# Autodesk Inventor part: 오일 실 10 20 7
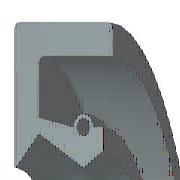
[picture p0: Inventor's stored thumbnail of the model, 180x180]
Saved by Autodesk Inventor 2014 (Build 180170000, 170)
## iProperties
IsCustomPart: 1
Created: 2012-02
Part Number: 오일 실 10 20 7
Material: 고무
Description: 오일-실
Document SubType Name: Modeling
Standard: KS B 2804
Designer: mduedu
Standards Organization: KS
Language: ko-KR
Size Designation: D - 10 20 7
Categories: <MemberInstance><Categories><Category DisplayName="샤프트 부품" InternalName="7f7aeb1f-a693-4053-b835-cee3144e0d98" Mnemonic="SHFT"><Category DisplayName="실링" Intern
Density: 0.93 g/cm^3
Mass: 1.11329 g
Surface Area: 16.3871 cm^2
Volume: 1.19708 cm^3
Appearance: Pink
Author: mduedu
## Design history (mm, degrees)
revolve "본체" stored, may be unused: angle "d17" = 90 deg
revolve "스프링1" stored, may be unused: angle "d18" = 90 deg
body "Solid1"
sketch "스케치1"
  geometry: L1 (0, 10)-(7, 10); L2 (7, 8.25)-(1.75, 8.25); L3 (1.75, 6.75)-(4.9, 5); L4 (4.9, 5)-(0, 5); L5 (0, 0)-(9.586, 0) reference; L6 (4.9, 5)-(6.3, 5.875); L7 (0, 18)-(0, -3) reference; L8 (-1.941, 0)-(11.507, 0) reference; L9 (4.2, 7.1)-(1.75, 7.59); L10 (1.75, 7.59)-(1.75, 8.25); L11 (0, 10)-(0, 5.088); L12 (4.9, 5)-(0, 5); L13 (1.75, 6.75)-(0.152, 5.028); L14 (7, 10)-(7, 8.25); L15 (5.6, 7.1)-(6.3, 7.1); L16 (6.3, 7.1)-(6.3, 5.875); C1 r 0.455 at (4.9, 7.1); A1 r 0.7 centre (4.9, 7.1) between (5.6, 7.1) and (4.2, 7.1); A2 r 0.088 centre (0.088, 5.088) between (0, 5.088) and (0.152, 5.028); 1 further point
  constraints: 28 end point, 5 horizontal alignment, 5 point on line, 4 point on circle, 4 vertical alignment, 3 centre point, 3 tangent, 2 collinear, 2 horizontal, 2 perpendicular, 1 coincident, 1 parallel
  dimensions: "d0" = 20 diameter of L1 L5 (= SD2); "d1" = 1.75 distance of L1.end L2.start (= SD); "d2" = 0.91 diameter of C1 (= SPDI); "d3" = 1.4 diameter of A1 (= SPDA); "d4" = 10 diameter of L3.end L5 (= NND); "d5" = 13.5 diameter of L3.start L5 (= TKDM); "d7" = 15.18 diameter of L9.end L5 (= TKDM + 0.24 x SWDT); "d8" = 1.75 distance between parallel lines of L11 L10 (= SD); "d9" = 4.9 distance from line of L11 C1.centre (= SPDST); "d10" = 14.2 diameter of C1.centre L5 (= HLDM); "d11" = 0.0875 radius of A2 (= 0.25 x LAB); "d12" = 6.3 distance between parallel lines of L11 L16 (= SDI); "d13" = 11.75 diameter of L6.end L5 (= ABDM); "d14" = 7 distance from line of L11 L1.end (= SWDT)
fillet "모깎기1" dims "d6" = 0.3 (= RR)
other parameters: "SD2" = 20 [user parameter; used in 1 equation term], "SWDT" = 7 [user parameter; used in 2 equation terms], "RR" = 0.3 [user parameter; used in 1 equation term], "SD" = 1.75 [user parameter; used in 2 equation terms], "NND" = 10 [user parameter; used in 1 equation term], "SPDA" = 1.4 [user parameter; used in 1 equation term], "SPDI" = 0.91 [user parameter; used in 1 equation term], "TKDM" = 13.5 [user parameter; used in 2 equation terms], "HLDM" = 14.2 [user parameter; used in 1 equation term], "ABDM" = 11.75 [user parameter; used in 1 equation term], "SDI" = 6.3 [user parameter; used in 1 equation term], "SPDST" = 4.9 [user parameter; used in 1 equation term], "LAB" = 0.35 [user parameter; used in 1 equation term], "d15" = 0, "d16" = 0, "d19" = 0
